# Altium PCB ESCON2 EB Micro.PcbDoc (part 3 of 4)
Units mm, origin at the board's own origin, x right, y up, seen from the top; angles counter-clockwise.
Board outline 75.6 x 72 mm, 8 copper layers (Top Side, Mid Layer 1, Mid Layer 2, Mid Layer 3, Mid Layer 4, Mid Layer 5, Mid Layer 6, Bottom Side), stack 1.555 mm thick; 192 components, 85 nets, 547 pads, 2387 vias.
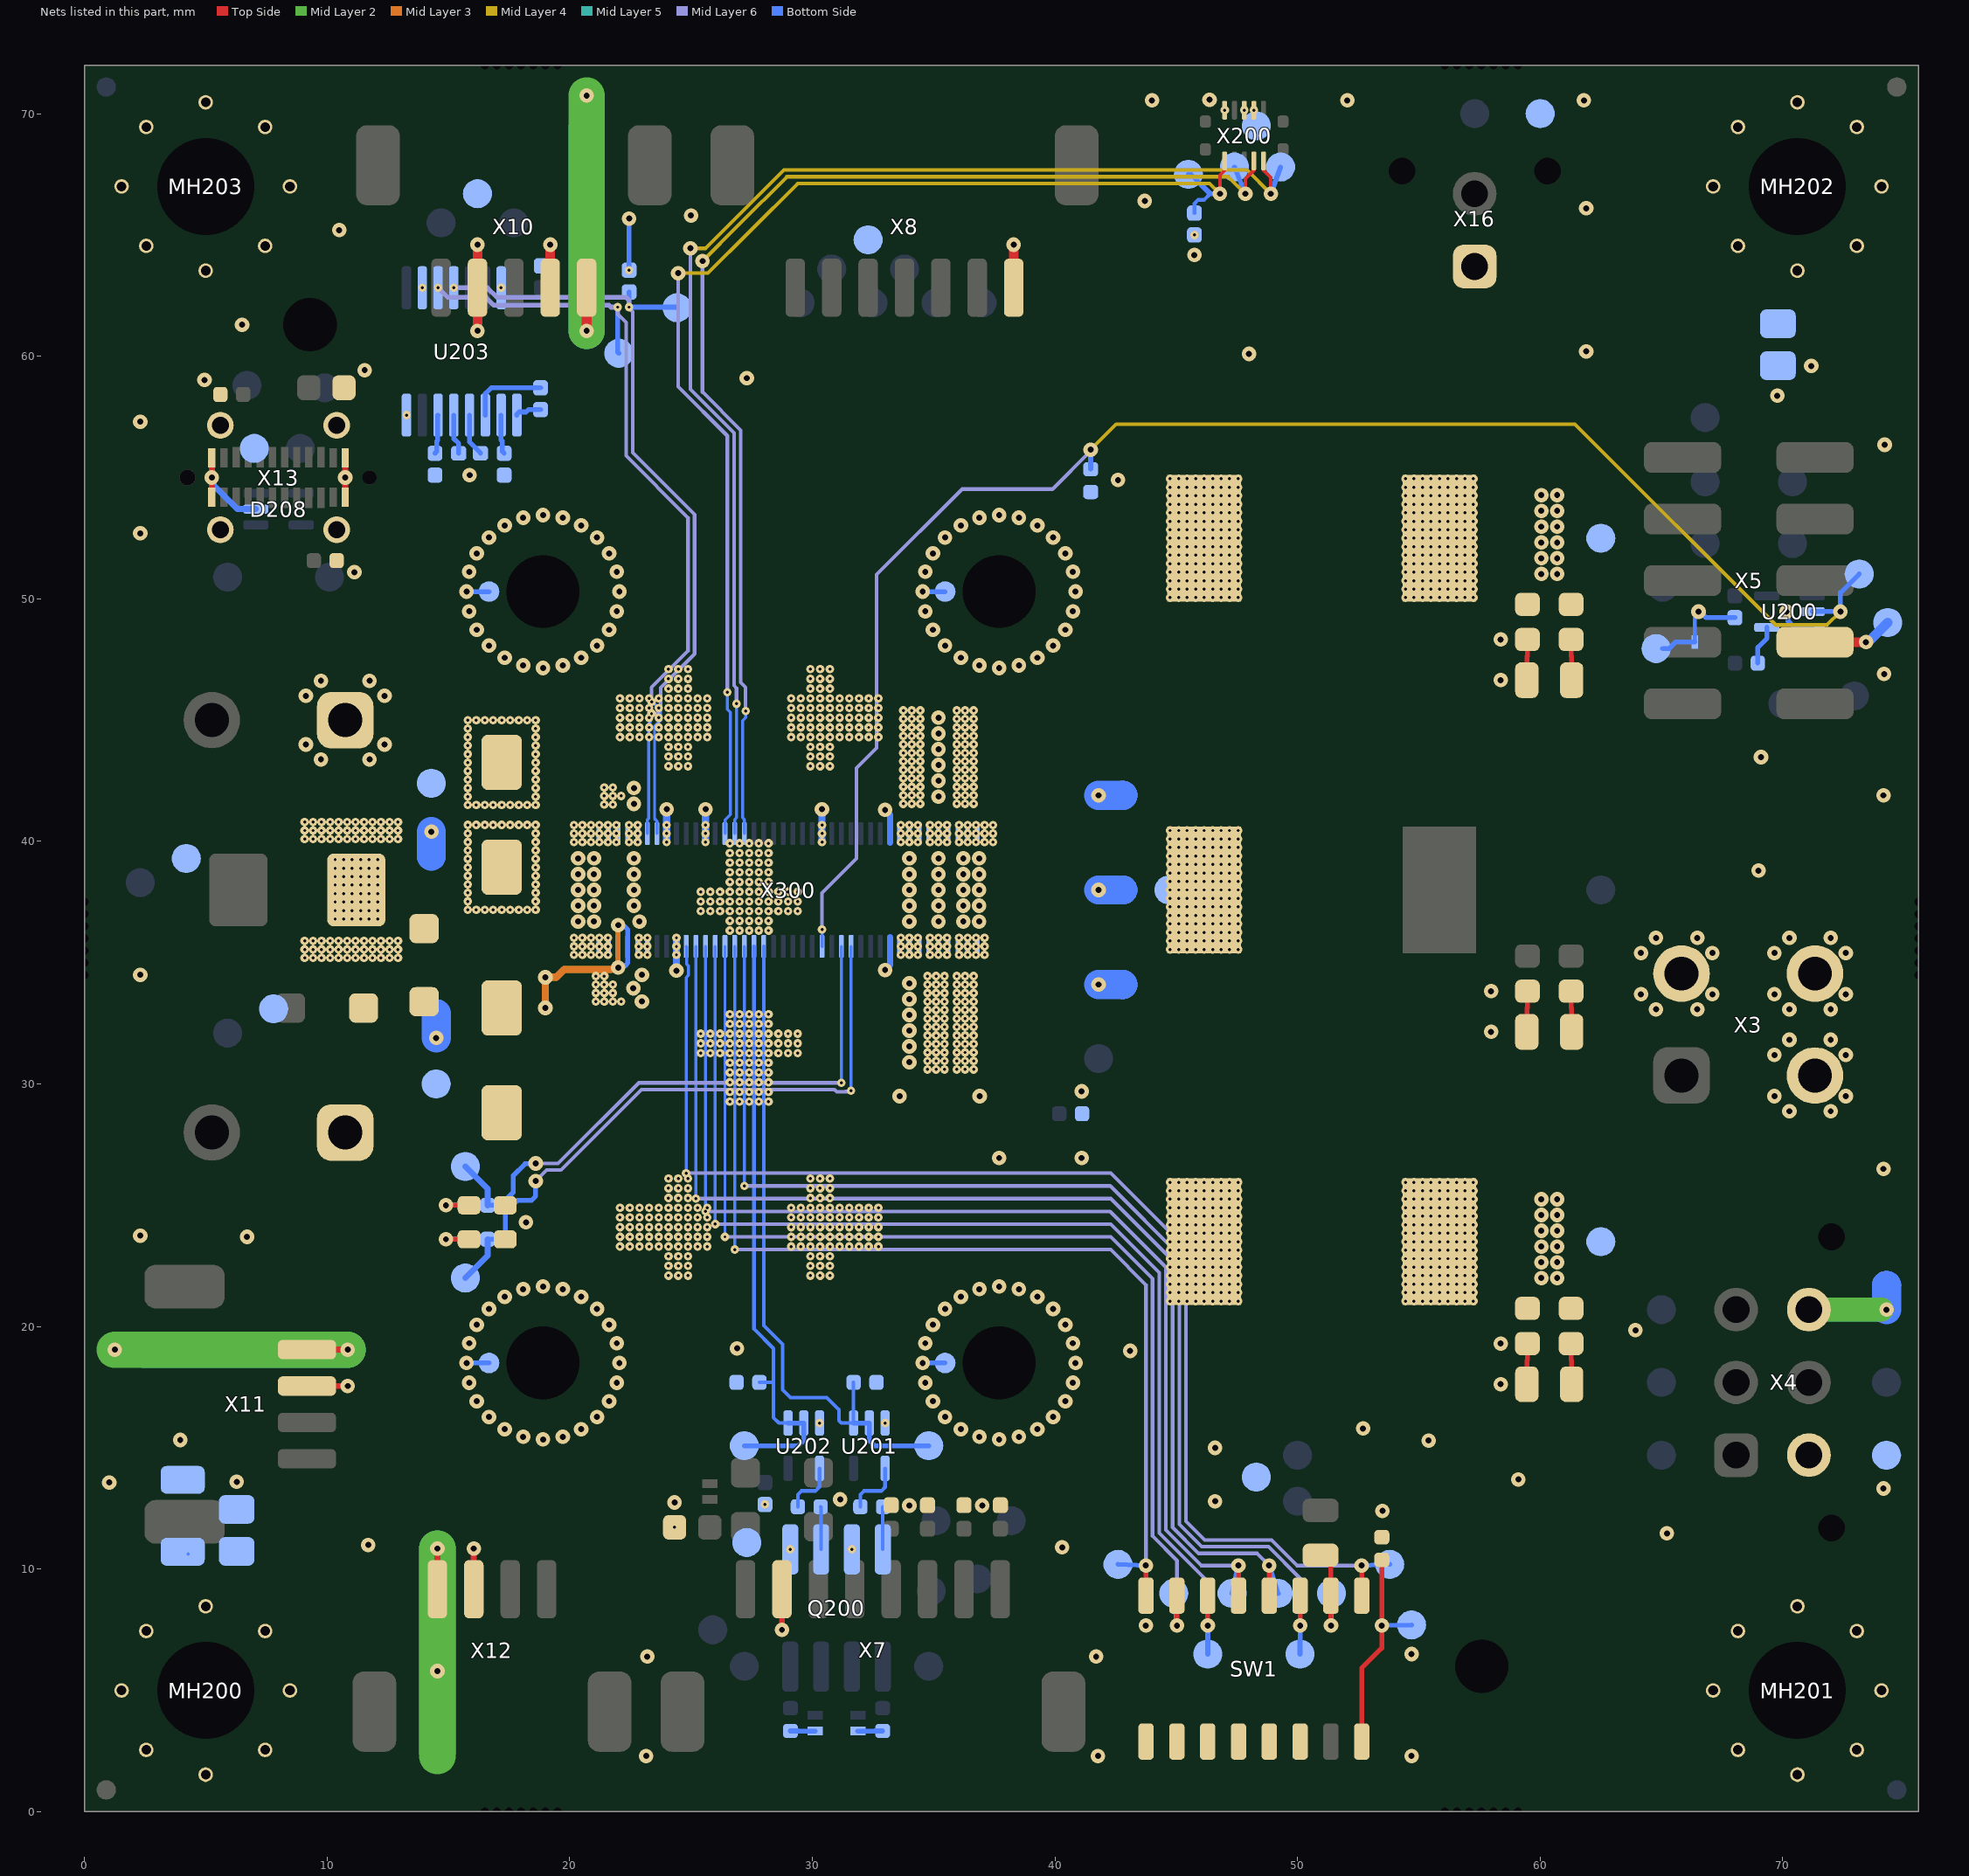
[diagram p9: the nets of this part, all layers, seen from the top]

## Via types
v1: diameter 0.35, hole 0.125, Top Side to Mid Layer 1, tented both sides, 1630 vias
v2: diameter 0.6, hole 0.25, Top Side to Bottom Side, 412 vias
v3: diameter 0.35, hole 0.125, Mid Layer 6 to Bottom Side, tented both sides, 345 vias

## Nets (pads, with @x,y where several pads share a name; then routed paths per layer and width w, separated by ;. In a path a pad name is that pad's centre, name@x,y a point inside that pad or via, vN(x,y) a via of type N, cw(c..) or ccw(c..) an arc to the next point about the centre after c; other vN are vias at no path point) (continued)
C_W2: C304.2 C307.2 L301.2 TP208.1 X3.2
  other v1: 54.45,50.05 54.8,50.05 55.15,50.05 55.5,50.05 55.85,50.05 56.2,50.05 56.55,50.05 56.9,50.05 57.25,50.05 54.45,50.4 54.8,50.4 55.15,50.4 55.5,50.4 55.85,50.4 56.2,50.4 56.55,50.4 56.9,50.4 57.25,50.4 54.45,50.75 54.8,50.75 55.15,50.75 55.5,50.75 55.85,50.75 56.2,50.75 56.55,50.75 56.9,50.75 57.25,50.75 54.45,51.1 54.8,51.1 55.15,51.1 55.5,51.1 55.85,51.1 56.2,51.1 56.55,51.1 56.9,51.1 57.25,51.1 54.45,51.45 54.8,51.45 55.15,51.45 55.5,51.45 55.85,51.45 56.2,51.45 56.55,51.45 56.9,51.45 57.25,51.45 54.45,51.8 54.8,51.8 55.15,51.8 55.5,51.8 55.85,51.8 56.2,51.8 56.55,51.8 56.9,51.8 57.25,51.8 54.45,52.15 54.8,52.15 55.15,52.15 55.5,52.15 55.85,52.15 56.2,52.15 56.55,52.15 56.9,52.15 57.25,52.15 54.45,52.5 54.8,52.5 55.15,52.5 55.5,52.5 55.85,52.5 56.2,52.5 56.55,52.5 56.9,52.5 57.25,52.5 54.45,52.85 54.8,52.85 55.15,52.85 55.5,52.85 55.85,52.85 56.2,52.85 56.55,52.85 56.9,52.85 57.25,52.85 54.45,53.2 54.8,53.2 55.15,53.2 55.5,53.2 55.85,53.2 56.2,53.2 56.55,53.2 56.9,53.2 57.25,53.2 54.45,53.55 54.8,53.55 55.15,53.55 55.5,53.55 55.85,53.55 56.2,53.55 56.55,53.55 56.9,53.55 57.25,53.55 54.45,53.9 54.8,53.9 55.15,53.9 55.5,53.9 55.85,53.9 56.2,53.9 56.55,53.9 56.9,53.9 57.25,53.9 54.45,54.25 54.8,54.25 55.15,54.25 55.5,54.25 55.85,54.25 56.2,54.25 56.55,54.25 56.9,54.25 57.25,54.25 54.45,54.6 54.8,54.6 55.15,54.6 55.5,54.6 55.85,54.6 56.2,54.6 56.55,54.6 56.9,54.6 57.25,54.6 54.45,54.95 54.8,54.95 55.15,54.95 55.5,54.95 55.85,54.95 56.2,54.95 56.55,54.95 56.9,54.95 57.25,54.95
  other v2: 64.775,33.078 66.475,33.078 64.153,33.7 67.097,33.7 64.153,35.4 67.097,35.4 64.775,36.022 66.475,36.022 60.05,51.025 60.7,51.025 60.05,51.675 60.7,51.675 60.05,52.325 60.7,52.325 60.05,52.975 60.7,52.975 60.05,53.625 60.7,53.625 60.05,54.275 60.7,54.275
C_W3: C305.2 C308.2 L302.2 TP209.1 X3.3
  other v1: 54.45,21.05 54.8,21.05 55.15,21.05 55.5,21.05 55.85,21.05 56.2,21.05 56.55,21.05 56.9,21.05 57.25,21.05 54.45,21.4 54.8,21.4 55.15,21.4 55.5,21.4 55.85,21.4 56.2,21.4 56.55,21.4 56.9,21.4 57.25,21.4 54.45,21.75 54.8,21.75 55.15,21.75 55.5,21.75 55.85,21.75 56.2,21.75 56.55,21.75 56.9,21.75 57.25,21.75 54.45,22.1 54.8,22.1 55.15,22.1 55.5,22.1 55.85,22.1 56.2,22.1 56.55,22.1 56.9,22.1 57.25,22.1 54.45,22.45 54.8,22.45 55.15,22.45 55.5,22.45 55.85,22.45 56.2,22.45 56.55,22.45 56.9,22.45 57.25,22.45 54.45,22.8 54.8,22.8 55.15,22.8 55.5,22.8 55.85,22.8 56.2,22.8 56.55,22.8 56.9,22.8 57.25,22.8 54.45,23.15 54.8,23.15 55.15,23.15 55.5,23.15 55.85,23.15 56.2,23.15 56.55,23.15 56.9,23.15 57.25,23.15 54.45,23.5 54.8,23.5 55.15,23.5 55.5,23.5 55.85,23.5 56.2,23.5 56.55,23.5 56.9,23.5 57.25,23.5 54.45,23.85 54.8,23.85 55.15,23.85 55.5,23.85 55.85,23.85 56.2,23.85 56.55,23.85 56.9,23.85 57.25,23.85 54.45,24.2 54.8,24.2 55.15,24.2 55.5,24.2 55.85,24.2 56.2,24.2 56.55,24.2 56.9,24.2 57.25,24.2 54.45,24.55 54.8,24.55 55.15,24.55 55.5,24.55 55.85,24.55 56.2,24.55 56.55,24.55 56.9,24.55 57.25,24.55 54.45,24.9 54.8,24.9 55.15,24.9 55.5,24.9 55.85,24.9 56.2,24.9 56.55,24.9 56.9,24.9 57.25,24.9 54.45,25.25 54.8,25.25 55.15,25.25 55.5,25.25 55.85,25.25 56.2,25.25 56.55,25.25 56.9,25.25 57.25,25.25 54.45,25.6 54.8,25.6 55.15,25.6 55.5,25.6 55.85,25.6 56.2,25.6 56.55,25.6 56.9,25.6 57.25,25.6 54.45,25.95 54.8,25.95 55.15,25.95 55.5,25.95 55.85,25.95 56.2,25.95 56.55,25.95 56.9,25.95 57.25,25.95
  other v2: 60.05,22 60.7,22 60.05,22.65 60.7,22.65 60.05,23.3 60.7,23.3 60.05,23.95 60.7,23.95 60.05,24.6 60.7,24.6 60.05,25.25 60.7,25.25 70.275,28.878 71.975,28.878 69.653,29.5 72.597,29.5 69.653,31.2 72.597,31.2 70.275,31.822 71.975,31.822
CAN_AutoBR: SW1.11 TP253.1 X300.49 | length 50.4
  Top Side w0.2: v2@50.105,7.68 SW1.11@50.105,8.907
  Mid Layer 6 w0.15: v3(27.2,25.8) 41.35,25.8 42.275,25.8 45.125,22.95 45.125,11.85 46.05,10.925 48.8,10.925 50.11,9.615 v2(50.11,7.675)
  Bottom Side w0.125: v3@27.2,25.783 X300.49@27.2,35.675
  Bottom Side w0.2: TP253.1@50.1,6.5 v2(50.11,7.675)
CAN_ID1: SW1.16 TP239.1 X300.51 | length 44
  Top Side w0.2: v2(43.75,10.15) 43.755,10.145 SW1.16@43.755,8.907
  Mid Layer 6 w0.15: v3(26.8,23.175) 41.85,23.175 42.3,23.175 43.75,21.725 v2(43.75,10.15)
  Bottom Side w0.125: v3(26.8,23.175) X300.51@26.8,35.675
  Bottom Side w0.2: TP239.1@42.6,10.2 v2(43.75,10.15)
CAN_ID2: SW1.15 TP243.1 X300.53 | length 47.6
  Top Side w0.2: SW1.15@45.025,8.907 45.025,7.68 v2(45.03,7.675)
  Mid Layer 6 w0.15: v3(26.4,23.7) 41.35,23.7 42.3,23.7 44.025,21.975 44.025,11.361 45.03,10.356 v2(45.03,7.675)
  Bottom Side w0.125: v3(26.4,23.7) X300.53@26.4,35.675
  Bottom Side w0.2: TP243.1@44.9,9 v2(45.03,7.675)
CAN_ID3: SW1.14 TP245.1 X300.55 | length 48.4
  Top Side w0.2: v2@46.295,7.68 SW1.14@46.295,8.907
  Mid Layer 6 w0.15: v3(26,24.225) 41.85,24.225 42.3,24.225 44.3,22.225 44.3,11.486 46.3,9.486 v2(46.3,7.675)
  Bottom Side w0.125: v3(26,24.225) X300.55@26,35.675
  Bottom Side w0.2: TP245.1@46.3,6.5 v2(46.3,7.675)
CAN_ID4: SW1.13 TP248.1 X300.57 | length 47.7
  Top Side w0.2: SW1.13@47.565,8.907 v2@47.565,10.145
  Mid Layer 6 w0.15: v3(25.6,24.75) 41.35,24.75 42.275,24.75 44.575,22.45 44.575,11.611 46.036,10.15 v2(47.56,10.15)
  Bottom Side w0.125: v3(25.6,24.75) X300.57@25.6,35.675
  Bottom Side w0.2: TP248.1@47.3,9 v2(47.56,10.15)
CAN_ID5: SW1.12 TP250.1 X300.59 | length 49.2
  Top Side w0.2: SW1.12@48.835,8.907 v2@48.835,10.145
  Mid Layer 6 w0.15: v3(25.2,25.275) 41.85,25.275 42.3,25.275 44.85,22.725 44.85,11.725 45.925,10.65 48.33,10.65 v2(48.83,10.15)
  Bottom Side w0.125: v3(25.2,25.275) X300.59@25.2,35.675
  Bottom Side w0.2: v2(48.83,10.15) TP250.1@49.2,9
CAN_ID6: SW1.9 TP257.1 X300.61 | length 53
  Top Side w0.2: SW1.9@52.645,8.907 v2@52.645,10.145
  Mid Layer 6 w0.15: v3(24.8,26.325) 41.85,26.325 42.3,26.325 45.4,23.225 45.4,11.975 46.175,11.2 48.925,11.2 49.975,10.15 v2(52.64,10.15)
  Bottom Side w0.125: v3(24.8,26.325) 24.8,34.386 24.888,34.473 24.888,34.877 24.825,34.939 24.825,35.65 X300.61@24.8,35.675
  Bottom Side w0.2: v2(52.64,10.15) TP257.1@53.8,10.2
DBG_SWCLK: TP222.1 X200.4 X300.50 | length 51.2
  Top Side w0.15: v2(47.85,66.7) 47.85,67.32 48.2,67.67 X200.4@48.2,68.055
  Mid Layer 6 w0.15: v2(25.475,63.925) 25.475,58.525 27.05,56.95 27.05,46.55 27.25,46.35 v3(27.25,45.375)
  Mid Layer 4 w0.15: v2(25.475,63.925) 26.975,65.425 28.95,67.4 47.15,67.4 v2(47.85,66.7)
  Bottom Side w0.125: X300.50@27.2,40.325 27.2,40.9 27.125,40.975 27.125,44.975 27.25,45.1 v3(27.25,45.375)
  Bottom Side w0.2: TP222.1@47.4,67.8 v2(47.85,66.7)
DBG_SWDIO: TP221.1 X200.2 X300.52 | length 53.3
  Top Side w0.15: X200.2@48.6,68.055 48.6,67.67 48.9,67.37 v2(48.9,66.7)
  Mid Layer 6 w0.15: v2(24.975,64.45) 24.975,58.636 26.775,56.836 26.775,46.425 26.875,46.325 v3(26.875,45.675)
  Mid Layer 4 w0.15: v2(24.975,64.45) 25.6,64.45 28.825,67.675 47.925,67.675 v2(48.9,66.7)
  Bottom Side w0.125: X300.52@26.8,40.325 26.8,40.9 26.875,40.975 v3(26.875,45.675)
  Bottom Side w0.2: v2(48.9,66.7) TP221.1@49.3,67.8
DigOUT1: R214.2 TP235.1 U201.1 U201.2 X300.45 | length 27.9
  Bottom Side w0.15: X300.45@28,35.675 28,20.05 28.775,19.275 28.775,17.4 29.1,17.075 30.6,17.075 31.1,16.575 31.1,16.125 31.2,16.025 U201.1@31.7,16.025 R214.2@31.7,17.7
  Bottom Side w0.2: U201.1@31.7,16.025 U201.2@32.35,16.025 32.35,15.315 32.575,15.09 TP235.1@34.8,15.09
DigOUT2: R215.2 TP236.1 U202.1 U202.2 X300.47 | length 24.9
  Bottom Side w0.15: X300.47@27.6,35.675 27.6,19.9 28.4,19.1 28.4,17.7 ; R215.2@27.82,17.7 28.4,17.7 ; U202.1@29,16.025 28.625,16.025 28.4,16.25 28.4,17.7
  Bottom Side w0.2: TP236.1@27.2,15.09 29.425,15.09 29.65,15.315 U202.2@29.65,16.025 U202.1@29,16.025
GND: C200.1 C201.1 C202.1 C203.1 C204.1 C205.1 C206.1 C207.2 C208.1 C209.2 C212.1 C300.2 C301.2 C302.2 C306.1 C307.1 C308.1 D200.1 D202.1 D203.1 D208.2 D209.1 D210.1 D302.2 D303.2 DS200.1 DS201.1 MP300.1 MP301.1 MP302.1 MP303.1 Q200.1 Q200.3 R206.1 R207.2 R208.2 R210.1 R213.1 R214.1 R215.1 R309.1 R310.1 R311.1 R324.1 SW1.1 SW1.2 SW1.3 SW1.4 SW1.5 SW1.6 TP200.1 TP203.1 TP204.1 TP214.1 TP226.1 TP227.1 TP238.1 TP242.1 TP246.1 TP259.1 TP264.1 TP265.1 TP304.1 TP313.1 TP314.1 U200.3 U201.3 U202.3 U203.8 U203.10 U203.15 X1.1 X2.1 X4.4 X5.3 X7.7 X8.7 X10.2 X10.4 X11.3 X12.3 X13.A1 X13.A12 X13.B1 X13.B12 X16.1 X200.3 X200.5 X200.9 X300.19 X300.20 X300.34 X300.58 X300.63 X300.66 X300.69 X300.71 X300.72 X300.74 | length 46.2
  Top Side w0.2: R311.1@59.45,17.625 59.45,18.6 59.475,18.625 C308.1@59.475,19.3 ; R309.1@59.45,32.15 59.45,33.125 59.475,33.15 C306.1@59.475,33.825 ; R310.1@59.45,46.65 59.45,47.625 59.475,47.65 C307.1@59.475,48.325
  Top Side w0.25: X13.B12@5.25,54.195 v2(5.25,55) X13.A1@5.25,55.805 ; X11.3@9.175,17.55 v2@10.85,17.55 ; X13.B1@10.75,54.195 X13.A12@10.75,55.805 ; X12.3@16.05,9.175 v2(16.05,10.85) ; v2(28.75,7.5) X7.7@28.75,9.175
  Top Side w0.4: v2(16.2,61.05) X10.2@16.2,62.825 v2(16.2,64.6) ; X10.4@19.2,62.825 v2(19.2,64.6) ; X8.7@38.3,62.825 v2(38.3,64.6) ; X5.3@71.33,48.21 v2@73.425,48.21
  Bottom Side w0.15: D200.1@66.375,48.225 66.375,49.203 66.525,49.353 v2(66.525,49.475)
  Bottom Side w0.2: v2(5.25,55) v2@5.327,54.923 ; v2(15.75,18.5) MP302.1@16.675,18.5 ; v2(15.75,50.3) MP301.1@16.675,50.3 ; v3(22.45,63.55) v2(22.45,65.675) ; v2(34.55,18.5) MP300.1@35.475,18.5 ; v2(34.55,50.3) MP303.1@35.475,50.3 ; TP203.1@65.05,47.95 65.321,47.95 65.596,48.225 D200.1@66.375,48.225 ; v2(66.525,49.475) 66.592,49.475 66.842,49.225 C200.1@68.025,49.225 ; v2(70.15,49.475) 70.212,49.413 70.212,49.088 70.475,48.825 U200.3@71.21,48.825
  Bottom Side w0.25: v2@5.327,54.923 5.327,54.673 6.3,53.7 D208.2@7.065,53.7 ; v2(33,34.7) 33.2,34.9 X300.19@33.2,35.675 X300.19@33.2,36.05 ; v2(33,41.3) 33.2,41.1 X300.20@33.2,40.325 X300.20@33.2,39.95
  Bottom Side w0.3: v3(24,39.975) v3(24,40.325) v2(24,41.325) ; v2(24.4,34.675) v3(24.4,35.675) v3(24.4,36.025) ; v3(25.6,39.975) v3(25.6,40.325) v2(25.6,41.325) ; v3(30.4,39.975) v3(30.4,40.325) v2(30.4,41.325)
  Bottom Side w0.4: v2(73.43,48.215) 73.468,48.253 73.553,48.253 TP214.1@74.325,49.025
  other v1: 24.325,11.725 29.925,22.1 30.325,22.1 30.725,22.1 29.925,22.5 30.325,22.5 30.725,22.5 29.925,22.9 30.325,22.9 30.725,22.9 29.125,23.3 29.525,23.3 29.925,23.3 30.325,23.3 30.725,23.3 31.125,23.3 31.525,23.3 31.925,23.3 32.325,23.3 32.725,23.3 29.125,23.7 29.525,23.7 29.925,23.7 30.325,23.7 30.725,23.7 31.125,23.7 31.525,23.7 31.925,23.7 32.325,23.7 32.725,23.7 29.125,24.1 29.525,24.1 29.925,24.1 30.325,24.1 30.725,24.1 31.125,24.1 31.525,24.1 31.925,24.1 32.325,24.1 32.725,24.1 29.125,24.5 29.525,24.5 29.925,24.5 30.325,24.5 30.725,24.5 31.125,24.5 31.525,24.5 31.925,24.5 32.325,24.5 32.725,24.5 29.125,24.9 29.525,24.9 29.925,24.9 30.325,24.9 30.725,24.9 31.125,24.9 31.525,24.9 31.925,24.9 32.325,24.9 32.725,24.9 29.925,25.3 30.325,25.3 30.725,25.3 29.925,25.7 30.325,25.7 30.725,25.7 29.925,26.1 30.325,26.1 30.725,26.1 26.6,36.325 27,36.325 27.4,36.325 27.8,36.325 28.2,36.325 26.6,36.725 27,36.725 27.4,36.725 27.8,36.725 28.2,36.725 25.4,37.125 25.8,37.125 26.2,37.125 26.6,37.125 27,37.125 27.4,37.125 27.8,37.125 28.2,37.125 28.6,37.125 29,37.125 29.4,37.125 25.4,37.525 25.8,37.525 26.2,37.525 26.6,37.525 27,37.525 27.4,37.525 27.8,37.525 28.2,37.525 28.6,37.525 29,37.525 29.4,37.525 25.4,37.925 25.8,37.925 26.2,37.925 26.6,37.925 27,37.925 27.4,37.925 27.8,37.925 28.2,37.925 28.6,37.925 29,37.925 29.4,37.925 26.6,38.325 27,38.325 27.4,38.325 27.8,38.325 28.2,38.325 26.6,38.725 27,38.725 27.4,38.725 27.8,38.725 28.2,38.725 26.6,39.125 27,39.125 27.4,39.125 27.8,39.125 28.2,39.125 26.6,39.525 27,39.525 27.4,39.525 27.8,39.525 28.2,39.525 26.6,39.925 27,39.925 27.4,39.925 27.8,39.925 28.2,39.925 15.8,41.5 16.15,41.5 16.5,41.5 16.85,41.5 17.2,41.5 17.55,41.5 17.9,41.5 18.25,41.5 18.6,41.5 15.8,41.85 18.6,41.85 15.8,42.2 18.6,42.2 15.8,42.55 18.6,42.55 15.8,42.9 18.6,42.9 29.925,43.1 30.325,43.1 30.725,43.1 15.8,43.25 18.6,43.25 29.925,43.5 30.325,43.5 30.725,43.5 15.8,43.6 18.6,43.6 29.925,43.9 30.325,43.9 30.725,43.9 15.8,43.95 18.6,43.95 15.8,44.3 18.6,44.3 29.125,44.3 29.525,44.3 29.925,44.3 30.325,44.3 30.725,44.3 31.125,44.3 31.525,44.3 31.925,44.3 32.325,44.3 32.725,44.3 15.8,44.65 18.6,44.65 29.125,44.7 29.525,44.7 29.925,44.7 30.325,44.7 30.725,44.7 31.125,44.7 31.525,44.7 31.925,44.7 32.325,44.7 32.725,44.7 15.8,45 16.15,45 16.5,45 16.85,45 17.2,45 17.55,45 17.9,45 18.25,45 18.6,45 29.125,45.1 29.525,45.1 29.925,45.1 30.325,45.1 30.725,45.1 31.125,45.1 31.525,45.1 31.925,45.1 32.325,45.1 32.725,45.1 29.125,45.5 29.525,45.5 29.925,45.5 30.325,45.5 30.725,45.5 31.125,45.5 31.525,45.5 31.925,45.5 32.325,45.5 32.725,45.5 29.125,45.9 29.525,45.9 29.925,45.9 30.325,45.9 30.725,45.9 31.125,45.9 31.525,45.9 31.925,45.9 32.325,45.9 32.725,45.9 29.925,46.3 30.325,46.3 30.725,46.3 29.925,46.7 30.325,46.7 30.725,46.7 29.925,47.1 30.325,47.1 30.725,47.1 47,70.145 47.8,70.145 48.2,70.145
  other v2: 23.2,6.4 41.7,6.4 54.7,6.5 43.75,7.675 40.3,10.9 11.7,11 65.225,11.475 53.5,12.4 34,12.625 37,12.625 24.325,12.75 46.6,12.8 31.15,12.875 1.025,13.575 6.275,13.6 59.1,13.7 46.6,15 55.4,15.3 3.95,15.325 18.9,15.35 37.7,15.35 18.085,15.457 19.715,15.457 36.885,15.457 38.515,15.457 17.325,15.772 20.475,15.772 36.125,15.772 39.275,15.772 52.7,15.8 16.673,16.273 21.127,16.273 35.473,16.273 39.927,16.273 16.172,16.925 21.628,16.925 34.972,16.925 40.428,16.925 10.85,17.55 58.375,17.625 15.857,17.685 21.943,17.685 34.657,17.685 40.743,17.685 22.05,18.5 40.85,18.5 43.1,19 26.9,19.1 58.375,19.3 15.857,19.315 21.943,19.315 34.657,19.315 40.743,19.315 63.925,19.85 16.172,20.075 21.628,20.075 34.972,20.075 40.428,20.075 16.673,20.727 21.127,20.727 35.473,20.727 39.927,20.727 17.325,21.228 20.475,21.228 36.125,21.228 39.275,21.228 18.085,21.543 19.715,21.543 36.885,21.543 38.515,21.543 18.9,21.65 37.7,21.65 6.7,23.7 18.2,24.3 37.7,26.95 41.1,26.95 33.6,29.5 36.9,29.5 41.1,29.7 57.975,32.15 22.975,33.4 57.975,33.825 22.625,33.95 22.975,34.5 22.875,36.7 22.65,37.35 22.65,38 22.65,38.65 69,38.8 22.65,39.3 22.65,41.55 22.65,42.2 9.75,43.378 11.75,43.378 69.1,43.475 9.128,44 12.372,44 9.128,46 12.372,46 9.75,46.622 11.75,46.622 58.375,46.65 18.9,47.15 37.7,47.15 18.085,47.257 19.715,47.257 36.885,47.257 38.515,47.257 17.325,47.572 20.475,47.572 36.125,47.572 39.275,47.572 16.673,48.073 21.127,48.073 35.473,48.073 39.927,48.073 58.375,48.325 16.172,48.725 21.628,48.725 34.972,48.725 40.428,48.725 15.857,49.485 21.943,49.485 34.657,49.485 40.743,49.485 22.05,50.3 40.85,50.3 11.125,51.1 15.857,51.115 21.943,51.115 34.657,51.115 40.743,51.115 16.172,51.875 21.628,51.875 34.972,51.875 40.428,51.875 16.673,52.527 21.127,52.527 35.473,52.527 39.927,52.527 17.325,53.028 20.475,53.028 36.125,53.028 39.275,53.028 18.085,53.343 19.715,53.343 36.885,53.343 38.515,53.343 18.9,53.45 37.7,53.45 42.6,54.9 10.75,55 15.875,55.1 69.775,58.375 4.95,59.025 27.3,59.1 11.55,59.425 71.175,59.6 48,60.1 61.9,60.2 6.5,61.3 45.75,64.175 10.5,65.2 25,65.8 61.9,66.1 43.7,66.4 46.375,70.575
  other v3: 29.095,10.82 31.635,10.82 28.05,12.675 30.3,16.025 33,16.025 21.075,33.4 21.425,33.4 21.775,33.4 22.125,33.4 21.075,33.75 21.425,33.75 21.775,33.75 21.075,34.1 21.425,34.1 21.775,34.1 21.075,34.45 21.425,34.45 22.85,35.325 23.2,35.325 24.4,35.325 22.85,35.675 23.2,35.675 22.85,36.025 23.2,36.025 22.45,39.975 22.8,39.975 22.45,40.325 22.8,40.325 22.45,40.675 22.8,40.675 24,40.675 25.6,40.675 30.4,40.675 21.425,41.525 21.775,41.525 21.425,41.875 21.775,41.875 22.125,41.875 21.425,42.225 21.775,42.225 13.275,57.575 13.925,62.825 17.175,62.825 45.75,65
LED_Axis_gn: R212.1 TP261.1 X300.29 | length 24.7
  Mid Layer 6 w0.15: v2(18.6,26.725) 19.525,26.725 22.85,30.05 v3(31.2,30.05)
  Bottom Side w0.125: v3(31.2,30.05) X300.29@31.2,35.675
  Bottom Side w0.2: R212.1@16.62,25 17.14,25 17.675,25.535 17.675,26.225 18.163,26.713 v2@18.588,26.713
  Bottom Side w0.25: TP261.1@15.7,26.6 16.62,25.68 R212.1@16.62,25
LED_Axis_rd: R211.1 TP258.1 X300.27 | length 26.4
  Mid Layer 6 w0.15: v2(18.6,26) 19.05,26.45 19.639,26.45 22.964,29.775 30.91,29.775 31.01,29.675 31.355,29.675 31.37,29.69 31.565,29.69 v3(31.6,29.725)
  Bottom Side w0.125: v3(31.6,29.725) X300.27@31.6,35.675
  Bottom Side w0.2: R211.1@16.62,23.6 17.1,23.6 17.35,23.85 17.35,24.7 17.85,25.2 18.425,25.2 18.6,25.375 v2(18.6,26)
  Bottom Side w0.25: TP258.1@15.7,22 16.62,22.92 R211.1@16.62,23.6
NetC208_2: C208.2 U203.2 | length 1.6
  Bottom Side w0.2: U203.2@17.175,57.575 17.175,56.55 17.225,56.5 17.225,56.075 C208.2@17.3,56
NetC209_1: C209.1 U203.6 | length 1.6
  Bottom Side w0.2: C209.1@14.45,56 14.516,56.066 14.516,56.491 14.565,56.54 14.565,57.565 U203.6@14.575,57.575
NetC210_1: C210.1 U203.1 | length 1.1
  Bottom Side w0.2: U203.1@17.825,57.575 17.825,57.608 17.92,57.703 18.203,57.703 18.3,57.8 C210.1@18.8,57.8
NetC210_2: C210.2 U203.3 | length 3.3
  Bottom Side w0.2: U203.3@16.525,57.575 16.525,58.46 16.765,58.7 C210.2@18.8,58.7
NetC211_1: C211.1 U203.4 | length 1.8
  Bottom Side w0.2: U203.4@15.875,57.575 15.875,56.467 16.325,56.017 C211.1@16.325,56
NetC211_2: C211.2 U203.5 | length 1.7
  Bottom Side w0.2: U203.5@15.225,57.575 15.225,56.6 15.425,56.4 C211.2@15.425,56
NetC303_1: C303.1 R309.2 | length 1.7
  Top Side w0.2: C303.1@61.275,33.825 61.275,33.15 61.3,33.125 R309.2@61.3,32.15
NetC304_1: C304.1 R310.2 | length 1.7
  Top Side w0.2: C304.1@61.275,48.325 61.275,47.65 61.3,47.625 R310.2@61.3,46.65
NetC305_1: C305.1 R311.2 | length 1.7
  Top Side w0.2: C305.1@61.275,19.3 61.275,18.625 61.3,18.6 R311.2@61.3,17.625
NetD204_1: D204.1 R202.2 | length 1
  Bottom Side w0.2: D204.1@31.875,3.325 32.585,3.325 32.59,3.33 R202.2@32.9,3.33
NetD205_1: D205.1 R203.2 | length 1
  Bottom Side w0.2: R203.2@29.1,3.33 29.41,3.33 29.415,3.325 D205.1@30.125,3.325
NetDS200_2: DS200.2 R211.2 | length 1.7
  Top Side w0.2: v2(14.9,23.6) DS200.2@15.855,23.6
  Bottom Side w0.2: v2(14.9,23.6) R211.2@15.68,23.6
NetDS201_2: DS201.2 R212.2 | length 1.7
  Top Side w0.2: v2(14.9,25) DS201.2@15.855,25
  Bottom Side w0.2: v2(14.9,25) R212.2@15.68,25
NetQ200_2: Q200.2 R205.2 | length 1.8
  Bottom Side w0.15: R205.2@30.345,12.575 30.365,12.555 Q200.2@30.365,10.82
NetQ200_4: Q200.4 R204.2 | length 1.8
  Bottom Side w0.15: Q200.4@32.905,10.82 32.905,12.56 R204.2@32.92,12.575
NetR200_1: R200.1 U200.4 | length 1.6
  Bottom Side w0.2: R200.1@68.97,47.35 68.97,47.995 69.35,48.375 69.35,48.815 U200.4@69.34,48.825
NetR204_1: R204.1 U201.4 | length 2.4
  Bottom Side w0.15: R204.1@31.98,12.575 31.98,13.08 32.125,13.225 32.85,13.225 33,13.375 U201.4@33,14.155
NetR205_1: R205.1 U202.4 | length 2.3
  Bottom Side w0.15: R205.1@29.405,12.575 29.405,13.08 29.55,13.225 30.125,13.225 30.3,13.4 U202.4@30.3,14.155
NetR209_1: R209.1 SW1.10 TP255.1 | length 4.4
  Top Side w0.2: R209.1@50.95,10.575 51.375,10.15 SW1.10@51.375,8.907 v2@51.375,7.68
  Bottom Side w0.2: v2(51.38,7.675) TP255.1@51.4,9
NetR210_2: R210.2 SW1.8 TP256.1 | length 9.1
  Top Side w0.2: SW1.8@52.645,2.893 52.645,5.92 53.475,6.75 v2(53.475,7.675) R210.2@53.475,10.38
  Bottom Side w0.2: v2(53.475,7.675) TP256.1@54.7,7.7
S2_Clock: R213.2 TP206.1 U200.2 X300.33 | length 66.1
  Mid Layer 6 w0.15: v3(30.4,36.375) 30.4,37.875 31.825,39.3 31.825,43.025 32.65,43.85 32.65,51 36.175,54.525 39.9,54.525 41.475,56.1 v2(41.475,56.15)
  Mid Layer 4 w0.15: v2(41.475,56.15) 42.525,57.2 61.428,57.2 69.703,48.925 71.825,48.925 v2(72.375,49.475)
  Bottom Side w0.125: X300.33@30.4,35.675 v3(30.4,36.375)
  Bottom Side w0.2: R213.2@41.475,55.345 v2(41.475,56.15) ; U200.2@71.21,49.475 v2(72.375,49.475) 72.375,50.25 TP206.1@73.15,51.025
SGND: C204.2 C205.2 MH200.2 MH200.3 MH200.4 MH200.5 MH200.6 MH200.7 MH200.8 MH200.9 MH201.2 MH201.3 MH201.4 MH201.5 MH201.6 MH201.7 MH201.8 MH201.9 MH202.2 MH202.3 MH202.4 MH202.5 MH202.6 MH202.7 MH202.8 MH202.9 MH203.2 MH203.3 MH203.4 MH203.5 MH203.6 MH203.7 MH203.8 MH203.9 R206.2 TP244.1 X3.4 X4.6 X10.5 X11.4 X12.4 X13.S1 X13.S2 X13.S3 X13.S4 | length 63.3
  Top Side w0.25: X11.4@9.65,19.05 v2@10.85,19.05 ; X12.4@14.55,9.65 v2(14.55,10.85)
  Top Side w0.4: v2(20.7,61.05) X10.5@20.7,62
  Mid Layer 2 w1: X4.6@71.075,20.7 v2@74.05,20.7
  Mid Layer 2 w1.5: v2(1.25,19.05) v2(10.85,19.05) ; 14.55,2.3 v2(14.55,10.85) ; v2(20.7,61.05) v2(20.7,70.75)
  Mid Layer 5 w1: X4.6@71.075,20.7 v2@74.05,20.7
  Mid Layer 5 w1.5: 2.475,19.05 v2(10.85,19.05) ; 14.55,2.475 v2(14.55,10.85) ; v2(20.7,61.05) 20.7,69.425
  Bottom Side w0.125: R206.2@4.275,10.62 R206.2@4.275,10.635
  Bottom Side w1.2: v2(74.275,20.7) TP244.1@74.275,21.7
  other v2: 23.15,2.3 41.775,2.3 54.7,2.3 14.55,5.8 74.15,13.325 2.3,23.75 74.15,26.5 70.275,33.078 71.975,33.078 69.653,33.7 72.597,33.7 2.3,34.5 69.653,35.4 72.597,35.4 70.275,36.022 71.975,36.022 74.15,41.9 74.175,46.9 2.3,52.7 74.2,56.35 2.3,57.3 44,70.55 52.05,70.55 61.8,70.55
SYS_/Reset: C203.2 TP228.1 X200.10 X300.54 | length 52.4
  Top Side w0.15: v2(46.8,66.7) 46.8,67.47 47,67.67 X200.10@47,68.055
  Mid Layer 6 w0.15: v2(24.475,63.425) 24.475,58.747 26.5,56.722 v3(26.5,46.15)
  Mid Layer 4 w0.15: v2(24.475,63.425) 25.7,63.425 27.425,65.15 29.4,67.125 46.375,67.125 v2(46.8,66.7)
  Bottom Side w0.125: X300.54@26.413,40.325 26.413,40.888 26.625,41.1 26.625,45.323 26.5,45.448 v3(26.5,46.15)
  Bottom Side w0.15: C203.2@45.75,65.9 45.75,66.3 45.9,66.45 46.15,66.45 46.4,66.7
  Bottom Side w0.2: TP228.1@45.5,67.5 45.6,67.5 46.4,66.7 v2(46.8,66.7)
U: L300.1 TP300.1 X300.1 X300.2 X300.3 X300.4 X300.5 X300.6 | length 1
  Bottom Side w1.2: v2(41.8,38) TP300.1@42.8,38
  other v1: 36.05,35.325 36.4,35.325 36.75,35.325 44.75,35.55 45.1,35.55 45.45,35.55 45.8,35.55 46.15,35.55 46.5,35.55 46.85,35.55 47.2,35.55 47.55,35.55 36.05,35.675 36.4,35.675 36.75,35.675 44.75,35.9 45.1,35.9 45.45,35.9 45.8,35.9 46.15,35.9 46.5,35.9 46.85,35.9 47.2,35.9 47.55,35.9 36.05,36.025 36.4,36.025 36.75,36.025 44.75,36.25 45.1,36.25 45.45,36.25 45.8,36.25 46.15,36.25 46.5,36.25 46.85,36.25 47.2,36.25 47.55,36.25 44.75,36.6 45.1,36.6 45.45,36.6 45.8,36.6 46.15,36.6 46.5,36.6 46.85,36.6 47.2,36.6 47.55,36.6 44.75,36.95 45.1,36.95 45.45,36.95 45.8,36.95 46.15,36.95 46.5,36.95 46.85,36.95 47.2,36.95 47.55,36.95 44.75,37.3 45.1,37.3 45.45,37.3 45.8,37.3 46.15,37.3 46.5,37.3 46.85,37.3 47.2,37.3 47.55,37.3 44.75,37.65 45.1,37.65 45.45,37.65 45.8,37.65 46.15,37.65 46.5,37.65 46.85,37.65 47.2,37.65 47.55,37.65 44.75,38 45.1,38 45.45,38 45.8,38 46.15,38 46.5,38 46.85,38 47.2,38 47.55,38 44.75,38.35 45.1,38.35 45.45,38.35 45.8,38.35 46.15,38.35 46.5,38.35 46.85,38.35 47.2,38.35 47.55,38.35 44.75,38.7 45.1,38.7 45.45,38.7 45.8,38.7 46.15,38.7 46.5,38.7 46.85,38.7 47.2,38.7 47.55,38.7 44.75,39.05 45.1,39.05 45.45,39.05 45.8,39.05 46.15,39.05 46.5,39.05 46.85,39.05 47.2,39.05 47.55,39.05 44.75,39.4 45.1,39.4 45.45,39.4 45.8,39.4 46.15,39.4 46.5,39.4 46.85,39.4 47.2,39.4 47.55,39.4 44.75,39.75 45.1,39.75 45.45,39.75 45.8,39.75 46.15,39.75 46.5,39.75 46.85,39.75 47.2,39.75 47.55,39.75 36.05,39.975 36.4,39.975 36.75,39.975 44.75,40.1 45.1,40.1 45.45,40.1 45.8,40.1 46.15,40.1 46.5,40.1 46.85,40.1 47.2,40.1 47.55,40.1 36.05,40.325 36.4,40.325 36.75,40.325 44.75,40.45 45.1,40.45 45.45,40.45 45.8,40.45 46.15,40.45 46.5,40.45 46.85,40.45 47.2,40.45 47.55,40.45 36.05,40.675 36.4,40.675 36.75,40.675
  other v2: 36.225,36.7 36.875,36.7 36.225,37.35 36.875,37.35 36.225,38 36.875,38 36.225,38.65 36.875,38.65 36.225,39.3 36.875,39.3
  other v3: 36.05,35.325 36.4,35.325 36.75,35.325 37.1,35.325 36.05,35.675 36.4,35.675 36.75,35.675 37.1,35.675 36.05,36.025 36.4,36.025 36.75,36.025 37.1,36.025 36.05,39.975 36.4,39.975 36.75,39.975 37.1,39.975 37.45,39.975 36.05,40.325 36.4,40.325 36.75,40.325 37.1,40.325 37.45,40.325 36.05,40.675 36.4,40.675 36.75,40.675 37.1,40.675 37.45,40.675
UART_RxD: C212.2 TP212.1 U203.12 X300.70 | length 34.1
  Mid Layer 6 w0.15: v3(22.45,62.025) 22.45,61.987 22.6,61.837 22.6,56.025 25.15,53.475 25.15,47.736 23.75,46.336 23.75,45.445 23.587,45.282 23.382,45.282 v3(23.374,45.274)
  Mid Layer 6 w0.2: v3(15.225,62.825) 16.61,62.825 17.01,62.425 22.325,62.425 22.45,62.3 v3(22.45,62.025)
  Bottom Side w0.125: X300.70@23.2,40.325 23.2,40.9 23.25,40.95 23.25,44.854 23.331,44.934 23.331,45.231 v3(23.374,45.274)
  Bottom Side w0.2: C212.2@22.45,62.65 v3(22.45,62.025) 24.4,62.025 TP212.1@24.425,62
UART_TxD: TP211.1 U203.11 X300.68 | length 33.5
  Mid Layer 6 w0.15: v3(21.975,62.025) 21.975,61.75 22.325,61.4 22.325,55.9 24.875,53.35 24.875,47.85 23.375,46.35 v3(23.375,45.75)
  Mid Layer 6 w0.2: v3(14.575,62.825) 14.975,62.425 16.55,62.425 16.875,62.1 21.625,62.1 21.7,62.025 v3(21.975,62.025)
  Bottom Side w0.125: v3(23.375,45.75) 23.411,45.75 23.736,45.424 23.736,44.986 23.5,44.75 23.5,40.936 23.6,40.836 X300.68@23.6,40.325
  Bottom Side w0.2: v3(21.975,62.025) 21.975,60.175 TP211.1@22.025,60.125
V: L301.1 TP301.1 X300.7 X300.8 X300.9 X300.10 X300.11 X300.12 | length 1
  Bottom Side w1.2: v2(41.8,41.9) TP301.1@42.8,41.9
  other v1: 33.75,41.55 34.1,41.55 34.45,41.55 33.75,41.9 34.1,41.9 34.45,41.9 33.75,42.25 34.1,42.25 34.45,42.25 33.75,42.6 34.1,42.6 34.45,42.6 33.75,42.95 34.1,42.95 34.45,42.95 33.75,43.3 34.1,43.3 34.45,43.3 33.75,43.65 34.1,43.65 34.45,43.65 33.75,44 34.1,44 34.45,44 33.75,44.35 34.1,44.35 34.45,44.35 33.75,44.7 34.1,44.7 34.45,44.7 33.75,45.05 34.1,45.05 34.45,45.05 33.75,45.4 34.1,45.4 34.45,45.4 44.75,50.05 45.1,50.05 45.45,50.05 45.8,50.05 46.15,50.05 46.5,50.05 46.85,50.05 47.2,50.05 47.55,50.05 44.75,50.4 45.1,50.4 45.45,50.4 45.8,50.4 46.15,50.4 46.5,50.4 46.85,50.4 47.2,50.4 47.55,50.4 44.75,50.75 45.1,50.75 45.45,50.75 45.8,50.75 46.15,50.75 46.5,50.75 46.85,50.75 47.2,50.75 47.55,50.75 44.75,51.1 45.1,51.1 45.45,51.1 45.8,51.1 46.15,51.1 46.5,51.1 46.85,51.1 47.2,51.1 47.55,51.1 44.75,51.45 45.1,51.45 45.45,51.45 45.8,51.45 46.15,51.45 46.5,51.45 46.85,51.45 47.2,51.45 47.55,51.45 44.75,51.8 45.1,51.8 45.45,51.8 45.8,51.8 46.15,51.8 46.5,51.8 46.85,51.8 47.2,51.8 47.55,51.8 44.75,52.15 45.1,52.15 45.45,52.15 45.8,52.15 46.15,52.15 46.5,52.15 46.85,52.15 47.2,52.15 47.55,52.15 44.75,52.5 45.1,52.5 45.45,52.5 45.8,52.5 46.15,52.5 46.5,52.5 46.85,52.5 47.2,52.5 47.55,52.5 44.75,52.85 45.1,52.85 45.45,52.85 45.8,52.85 46.15,52.85 46.5,52.85 46.85,52.85 47.2,52.85 47.55,52.85 44.75,53.2 45.1,53.2 45.45,53.2 45.8,53.2 46.15,53.2 46.5,53.2 46.85,53.2 47.2,53.2 47.55,53.2 44.75,53.55 45.1,53.55 45.45,53.55 45.8,53.55 46.15,53.55 46.5,53.55 46.85,53.55 47.2,53.55 47.55,53.55 44.75,53.9 45.1,53.9 45.45,53.9 45.8,53.9 46.15,53.9 46.5,53.9 46.85,53.9 47.2,53.9 47.55,53.9 44.75,54.25 45.1,54.25 45.45,54.25 45.8,54.25 46.15,54.25 46.5,54.25 46.85,54.25 47.2,54.25 47.55,54.25 44.75,54.6 45.1,54.6 45.45,54.6 45.8,54.6 46.15,54.6 46.5,54.6 46.85,54.6 47.2,54.6 47.55,54.6 44.75,54.95 45.1,54.95 45.45,54.95 45.8,54.95 46.15,54.95 46.5,54.95 46.85,54.95 47.2,54.95 47.55,54.95
  other v2: 35.2,36.7 35.2,37.35 35.2,38 35.2,38.65 35.2,39.3 35.2,41.85 35.2,42.5 35.2,43.15 35.2,43.8 35.2,44.45 35.2,45.1
  other v3: 34.85,35.325 35.2,35.325 35.55,35.325 34.85,35.675 35.2,35.675 35.55,35.675 34.85,36.025 35.2,36.025 35.55,36.025 34.85,39.975 35.2,39.975 35.55,39.975 34.85,40.325 35.2,40.325 35.55,40.325 34.85,40.675 35.2,40.675 35.55,40.675 33.75,41.55 34.1,41.55 34.45,41.55 35.95,41.55 36.3,41.55 36.65,41.55 33.75,41.9 34.1,41.9 34.45,41.9 35.95,41.9 36.3,41.9 36.65,41.9 33.75,42.25 34.1,42.25 34.45,42.25 35.95,42.25 36.3,42.25 36.65,42.25 33.75,42.6 34.1,42.6 34.45,42.6 35.95,42.6 36.3,42.6 36.65,42.6 33.75,42.95 34.1,42.95 34.45,42.95 35.95,42.95 36.3,42.95 36.65,42.95 33.75,43.3 34.1,43.3 34.45,43.3 35.95,43.3 36.3,43.3 36.65,43.3 33.75,43.65 34.1,43.65 34.45,43.65 35.95,43.65 36.3,43.65 36.65,43.65 33.75,44 34.1,44 34.45,44 35.95,44 36.3,44 36.65,44 33.75,44.35 34.1,44.35 34.45,44.35 35.95,44.35 36.3,44.35 36.65,44.35 33.75,44.7 34.1,44.7 34.45,44.7 35.95,44.7 36.3,44.7 36.65,44.7 33.75,45.05 34.1,45.05 34.45,45.05 35.95,45.05 36.3,45.05 36.65,45.05 33.75,45.4 34.1,45.4 34.45,45.4 35.95,45.4 36.3,45.4 36.65,45.4
VL: D300.1 D301.1 D303.1 TP315.1 X300.73 X300.75 | length 17.4
  Mid Layer 3 w0.2: v2(22,34.8) 22,35.675 v2(22,36.55)
  Mid Layer 3 w0.3: v2(19,33.135) v2(19,34.4) 19.005,34.405 19.455,34.405 19.774,34.724 21.712,34.724 21.73,34.743 21.943,34.743 v2(22,34.8)
  Mid Layer 4 w0.2: v2(22,34.8) v2(22,36.55)
  Mid Layer 4 w0.3: v2(19,33.135) v2(19,34.4) 19.005,34.405 19.455,34.405 19.774,34.724 21.712,34.724 21.73,34.743 21.943,34.743 v2(22,34.8)
  Bottom Side w0.2: v2(22,34.8) 22.077,34.877 22.284,34.877 22.4,34.992 X300.73@22.4,35.675 22.4,36.358 22.284,36.473 22.077,36.473 v2(22,36.55) X300.75@22,35.675 v2(22,34.8)
  Bottom Side w1.2: v2(14.5,31.9) TP315.1@14.5,32.9
VP: C300.1 C301.1 C302.1 D301.2 D302.1 F300.2 TP316.1 X300.76 X300.77 X300.78 X300.79 X300.80 | length 1
  Bottom Side w1.2: TP316.1@14.3,39.4 v2(14.3,40.4)
  other v1: 24.075,22.1 24.475,22.1 24.875,22.1 24.075,22.5 24.475,22.5 24.875,22.5 24.075,22.9 24.475,22.9 24.875,22.9 22.075,23.3 22.475,23.3 22.875,23.3 23.275,23.3 23.675,23.3 24.075,23.3 24.475,23.3 24.875,23.3 25.275,23.3 25.675,23.3 22.075,23.7 22.475,23.7 22.875,23.7 23.275,23.7 23.675,23.7 24.075,23.7 24.475,23.7 24.875,23.7 25.275,23.7 25.675,23.7 22.075,24.1 22.475,24.1 22.875,24.1 23.275,24.1 23.675,24.1 24.075,24.1 24.475,24.1 24.875,24.1 25.275,24.1 25.675,24.1 22.075,24.5 22.475,24.5 22.875,24.5 23.275,24.5 23.675,24.5 24.075,24.5 24.475,24.5 24.875,24.5 25.275,24.5 25.675,24.5 22.075,24.9 22.475,24.9 22.875,24.9 23.275,24.9 23.675,24.9 24.075,24.9 24.475,24.9 24.875,24.9 25.275,24.9 25.675,24.9 24.075,25.3 24.475,25.3 24.875,25.3 24.075,25.7 24.475,25.7 24.875,25.7 24.075,26.1 24.475,26.1 24.875,26.1 26.6,29.275 27,29.275 27.4,29.275 27.8,29.275 28.2,29.275 26.6,29.675 27,29.675 27.4,29.675 27.8,29.675 28.2,29.675 26.6,30.075 27,30.075 27.4,30.075 27.8,30.075 28.2,30.075 26.6,30.475 27,30.475 27.4,30.475 27.8,30.475 28.2,30.475 26.6,30.875 27,30.875 27.4,30.875 27.8,30.875 28.2,30.875 25.4,31.275 25.8,31.275 26.2,31.275 26.6,31.275 27,31.275 27.4,31.275 27.8,31.275 28.2,31.275 28.6,31.275 29,31.275 29.4,31.275 25.4,31.675 25.8,31.675 26.2,31.675 26.6,31.675 27,31.675 27.4,31.675 27.8,31.675 28.2,31.675 28.6,31.675 29,31.675 29.4,31.675 25.4,32.075 25.8,32.075 26.2,32.075 26.6,32.075 27,32.075 27.4,32.075 27.8,32.075 28.2,32.075 28.6,32.075 29,32.075 29.4,32.075 26.6,32.475 27,32.475 27.4,32.475 27.8,32.475 28.2,32.475 26.6,32.875 27,32.875 27.4,32.875 27.8,32.875 28.2,32.875 9.075,35.2 9.425,35.2 9.775,35.2 10.125,35.2 10.475,35.2 10.825,35.2 11.175,35.2 11.525,35.2 11.875,35.2 12.225,35.2 12.575,35.2 12.925,35.2 9.075,35.55 9.425,35.55 9.775,35.55 10.125,35.55 10.475,35.55 10.825,35.55 11.175,35.55 11.525,35.55 11.875,35.55 12.225,35.55 12.575,35.55 12.925,35.55 9.075,35.9 9.425,35.9 9.775,35.9 10.125,35.9 10.475,35.9 10.825,35.9 11.175,35.9 11.525,35.9 11.875,35.9 12.225,35.9 12.575,35.9 12.925,35.9 10.335,36.8 10.685,36.8 11.035,36.8 11.385,36.8 11.735,36.8 12.085,36.8 10.335,37.15 10.685,37.15 11.035,37.15 11.385,37.15 11.735,37.15 12.085,37.15 15.8,37.18 16.15,37.18 16.5,37.18 16.85,37.18 17.2,37.18 17.55,37.18 17.9,37.18 18.25,37.18 18.6,37.18 10.335,37.5 10.685,37.5 11.035,37.5 11.385,37.5 11.735,37.5 12.085,37.5 15.8,37.53 18.6,37.53 10.335,37.85 10.685,37.85 11.035,37.85 11.385,37.85 11.735,37.85 12.085,37.85 15.8,37.88 18.6,37.88 10.335,38.2 10.685,38.2 11.035,38.2 11.385,38.2 11.735,38.2 12.085,38.2 15.8,38.23 18.6,38.23 10.335,38.55 10.685,38.55 11.035,38.55 11.385,38.55 11.735,38.55 12.085,38.55 15.8,38.58 18.6,38.58 10.335,38.9 10.685,38.9 11.035,38.9 11.385,38.9 11.735,38.9 12.085,38.9 15.8,38.93 18.6,38.93 10.335,39.25 10.685,39.25 11.035,39.25 11.385,39.25 11.735,39.25 12.085,39.25 15.8,39.28 18.6,39.28 15.8,39.63 18.6,39.63 15.8,39.98 18.6,39.98 9.075,40.1 9.425,40.1 9.775,40.1 10.125,40.1 10.475,40.1 10.825,40.1 11.175,40.1 11.525,40.1 11.875,40.1 12.225,40.1 12.575,40.1 12.925,40.1 15.8,40.33 18.6,40.33 9.075,40.45 9.425,40.45 9.775,40.45 10.125,40.45 10.475,40.45 10.825,40.45 11.175,40.45 11.525,40.45 11.875,40.45 12.225,40.45 12.575,40.45 12.925,40.45 15.8,40.68 16.15,40.68 16.5,40.68 16.85,40.68 17.2,40.68 17.55,40.68 17.9,40.68 18.25,40.68 18.6,40.68 9.075,40.8 9.425,40.8 9.775,40.8 10.125,40.8 10.475,40.8 10.825,40.8 11.175,40.8 11.525,40.8 11.875,40.8 12.225,40.8 12.575,40.8 12.925,40.8 24.075,43.1 24.475,43.1 24.875,43.1 24.075,43.5 24.475,43.5 24.875,43.5 24.075,43.9 24.475,43.9 24.875,43.9 22.075,44.3 22.475,44.3 22.875,44.3 23.275,44.3 23.675,44.3 24.075,44.3 24.475,44.3 24.875,44.3 25.275,44.3 25.675,44.3 22.075,44.7 22.475,44.7 22.875,44.7 23.275,44.7 23.675,44.7 24.075,44.7 24.475,44.7 24.875,44.7 25.275,44.7 25.675,44.7 22.075,45.1 22.475,45.1 22.875,45.1 23.275,45.1 23.675,45.1 24.075,45.1 24.475,45.1 24.875,45.1 25.275,45.1 25.675,45.1 22.075,45.5 22.475,45.5 22.875,45.5 23.275,45.5 23.675,45.5 24.075,45.5 24.475,45.5 24.875,45.5 25.275,45.5 25.675,45.5 22.075,45.9 22.475,45.9 22.875,45.9 23.275,45.9 23.675,45.9 24.075,45.9 24.475,45.9 24.875,45.9 25.275,45.9 25.675,45.9 24.075,46.3 24.475,46.3 24.875,46.3 24.075,46.7 24.475,46.7 24.875,46.7 24.075,47.1 24.475,47.1 24.875,47.1
  other v2: 20.35,36.7 21,36.7 20.35,37.35 21,37.35 20.35,38 21,38 20.35,38.65 21,38.65 20.35,39.3 21,39.3
  other v3: 20.175,35.325 20.525,35.325 20.875,35.325 21.225,35.325 21.575,35.325 20.175,35.675 20.525,35.675 20.875,35.675 21.225,35.675 21.575,35.675 20.175,36.025 20.525,36.025 20.875,36.025 21.225,36.025 21.575,36.025 20.175,39.975 20.525,39.975 20.875,39.975 21.225,39.975 21.575,39.975 21.925,39.975 20.175,40.325 20.525,40.325 20.875,40.325 21.225,40.325 21.575,40.325 21.925,40.325 20.175,40.675 20.525,40.675 20.875,40.675 21.225,40.675 21.575,40.675 21.925,40.675
W: L302.1 TP302.1 X300.13 X300.14 X300.15 X300.16 X300.17 X300.18 | length 1
  Bottom Side w1.2: v2(41.8,34.1) TP302.1@42.8,34.1
  other v1: 44.75,21.05 45.1,21.05 45.45,21.05 45.8,21.05 46.15,21.05 46.5,21.05 46.85,21.05 47.2,21.05 47.55,21.05 44.75,21.4 45.1,21.4 45.45,21.4 45.8,21.4 46.15,21.4 46.5,21.4 46.85,21.4 47.2,21.4 47.55,21.4 44.75,21.75 45.1,21.75 45.45,21.75 45.8,21.75 46.15,21.75 46.5,21.75 46.85,21.75 47.2,21.75 47.55,21.75 44.75,22.1 45.1,22.1 45.45,22.1 45.8,22.1 46.15,22.1 46.5,22.1 46.85,22.1 47.2,22.1 47.55,22.1 44.75,22.45 45.1,22.45 45.45,22.45 45.8,22.45 46.15,22.45 46.5,22.45 46.85,22.45 47.2,22.45 47.55,22.45 44.75,22.8 45.1,22.8 45.45,22.8 45.8,22.8 46.15,22.8 46.5,22.8 46.85,22.8 47.2,22.8 47.55,22.8 44.75,23.15 45.1,23.15 45.45,23.15 45.8,23.15 46.15,23.15 46.5,23.15 46.85,23.15 47.2,23.15 47.55,23.15 44.75,23.5 45.1,23.5 45.45,23.5 45.8,23.5 46.15,23.5 46.5,23.5 46.85,23.5 47.2,23.5 47.55,23.5 44.75,23.85 45.1,23.85 45.45,23.85 45.8,23.85 46.15,23.85 46.5,23.85 46.85,23.85 47.2,23.85 47.55,23.85 44.75,24.2 45.1,24.2 45.45,24.2 45.8,24.2 46.15,24.2 46.5,24.2 46.85,24.2 47.2,24.2 47.55,24.2 44.75,24.55 45.1,24.55 45.45,24.55 45.8,24.55 46.15,24.55 46.5,24.55 46.85,24.55 47.2,24.55 47.55,24.55 44.75,24.9 45.1,24.9 45.45,24.9 45.8,24.9 46.15,24.9 46.5,24.9 46.85,24.9 47.2,24.9 47.55,24.9 44.75,25.25 45.1,25.25 45.45,25.25 45.8,25.25 46.15,25.25 46.5,25.25 46.85,25.25 47.2,25.25 47.55,25.25 44.75,25.6 45.1,25.6 45.45,25.6 45.8,25.6 46.15,25.6 46.5,25.6 46.85,25.6 47.2,25.6 47.55,25.6 44.75,25.95 45.1,25.95 45.45,25.95 45.8,25.95 46.15,25.95 46.5,25.95 46.85,25.95 47.2,25.95 47.55,25.95 34.75,30.6 35.1,30.6 35.45,30.6 34.75,30.95 35.1,30.95 35.45,30.95 34.75,31.3 35.1,31.3 35.45,31.3 34.75,31.65 35.1,31.65 35.45,31.65 34.75,32 35.1,32 35.45,32 34.75,32.35 35.1,32.35 35.45,32.35 34.75,32.7 35.1,32.7 35.45,32.7 34.75,33.05 35.1,33.05 35.45,33.05 34.75,33.4 35.1,33.4 35.45,33.4 34.75,33.75 35.1,33.75 35.45,33.75 34.75,34.1 35.1,34.1 35.45,34.1 34.75,34.45 35.1,34.45 35.45,34.45
  other v2: 34,30.9 34,31.55 34,32.2 34,32.85 34,33.5 34,34.15 34,36.7 34,37.35 34,38 34,38.65 34,39.3
  other v3: 34.75,30.6 35.1,30.6 35.45,30.6 35.95,30.6 36.3,30.6 36.65,30.6 34.75,30.95 35.1,30.95 35.45,30.95 35.95,30.95 36.3,30.95 36.65,30.95 34.75,31.3 35.1,31.3 35.45,31.3 35.95,31.3 36.3,31.3 36.65,31.3 34.75,31.65 35.1,31.65 35.45,31.65 35.95,31.65 36.3,31.65 36.65,31.65 34.75,32 35.1,32 35.45,32 35.95,32 36.3,32 36.65,32 34.75,32.35 35.1,32.35 35.45,32.35 35.95,32.35 36.3,32.35 36.65,32.35 34.75,32.7 35.1,32.7 35.45,32.7 35.95,32.7 36.3,32.7 36.65,32.7 34.75,33.05 35.1,33.05 35.45,33.05 35.95,33.05 36.3,33.05 36.65,33.05 34.75,33.4 35.1,33.4 35.45,33.4 35.95,33.4 36.3,33.4 36.65,33.4 34.75,33.75 35.1,33.75 35.45,33.75 35.95,33.75 36.3,33.75 36.65,33.75 34.75,34.1 35.1,34.1 35.45,34.1 35.95,34.1 36.3,34.1 36.65,34.1 34.75,34.45 35.1,34.45 35.45,34.45 35.95,34.45 36.3,34.45 36.65,34.45 33.65,35.325 34,35.325 34.35,35.325 33.65,35.675 34,35.675 34.35,35.675 33.65,36.025 34,36.025 34.35,36.025 33.65,39.975 34,39.975 34.35,39.975 33.65,40.325 34,40.325 34.35,40.325 33.65,40.675 34,40.675 34.35,40.675
pads on no net: FD200.1 FD201.1 FD202.1 FD203.1 MH200.1 MH201.1 MH202.1 MH203.1 MH204.1 MH205.1 MP300.0 MP301.0 MP302.0 MP303.0 STEG200.0 STEG201.0 STEG202.0 STEG203.0 STEG204.0 STEG205.0 U200.1 U203.7 U203.9 X4.0 X5.9 X7.0 X8.0 X10.0 X11.0 X12.0 X13.0 X13.A2 X13.A3 X13.A8 X13.A10 X13.A11 X13.B2 X13.B3 X13.B8 X13.B10 X13.B11 X16.0 X200.0 X200.6 X200.7 X200.8

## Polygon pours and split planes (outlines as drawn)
GND on Bottom Side "B_GND-001" (solid, remove dead copper, pour order 329): 0,0 0,72 75.575,72 75.575,0
SGND on Bottom Side "B_SGND-001" (solid, remove dead copper, pour order 242): 68.675,37.35 73.275,37.35 73.275,32.55 68.675,32.55
C_VP on Bottom Side "B_C_VP-001" (solid, remove dead copper, pour order 241): 7.9,42.2 0,42.2 0,47.8 7.9,47.8
C_W1 on Bottom Side "B_C_W1-003" (solid, pour order 201): 68.275,32.35 68.275,27.55 63.225,27.55 63.225,32.35
C_W3 on Bottom Side "B_C_W3-001" (solid, remove dead copper, pour order 198): 68.475,32.35 73.275,32.35 73.275,27.35 68.475,27.35
C_W2 on Bottom Side "B_C_W2-001" (solid, remove dead copper, pour order 197): 68.275,41.5 68.275,32.55 63.475,32.55 63.475,41.5
GND on Bottom Side "B_GND-003" (solid, remove dead copper, pour order 229): 22.3,38 23.3,38 23.3,33.075 22.3,33.075
VP on Bottom Side "B_VP_m-001" (solid, remove dead copper, pour order 228): 19.6,41 22.1,41 22.1,35 19.6,35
